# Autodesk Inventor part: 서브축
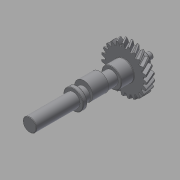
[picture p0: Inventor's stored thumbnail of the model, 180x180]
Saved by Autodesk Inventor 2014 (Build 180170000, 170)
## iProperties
Created: 2016-12
Part Number: 서브축
Material: 강철, 탄소
Document SubType Name: Modeling
Designer: mduedu
Categories: <?xml version="1.0" encoding="UTF-16"?> <MemberInstance><Categories><FamilyTemplate><FamilyTemplateParameter ValueType="xs:double" Id="1" ObjectReferenceKey="da
Density: 7.87 g/cm^3
Appearance: 기본값
Mass: 483.642 g
Surface Area: 167.142 cm^2
Volume: 61.4539 cm^3
CustomPartVersion: 1
Author: mduedu
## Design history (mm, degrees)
sketch "Sketch1"
  geometry: C1 r 28.558 at (0, 0)
  constraints: 1 centre point
  dimensions: "d0" = 57.11622 diameter of C1 (= da_da)
extrude "Extrusion1" new body sketch "Sketch1" distance "d1" = 10 (= da_b); taper "d2" = 0 deg
workplane "Work Plane2"
sketch "Sketch2"
  geometry: C1 r 28.558 at (0, 0) reference; C2 r 26.558 at (0, 0)
  constraints: 1 centre point, 1 coincident
  dimensions: "d3" = 53.11622 diameter of C2 (= da_dw)
feature "피치 지름" sketch "Sketch2" dims "d4" = 10, "d5" = 0
workplane "Work Plane8"
workplane "Work Plane9"
feature "스퍼 기어" dims "da_b" = 10, "da_d" = 53.11622, "da_aw" = 43.87862, "da_da" = 57.11622, "da_df" = 48.11622, "da_dw" = 53.11622, angle "da_beta" = 30 deg, "da_lefttooth" = 10, "da_righttooth" = 0
sketch "스케치3"
  geometry: C1 r 12.5 at (0, 0); 1 further point
  constraints: 1 centre point, 1 coincident
  dimensions: "d49" = 25 diameter of C1
extrude "돌출2" join sketch "스케치3" distance "d50" = 16; taper "d51" = 0 deg
sketch "스케치4"
  geometry: C1 r 8.5 at (0, 0); 1 further point
  constraints: 1 centre point, 1 coincident
  dimensions: "d52" = 17 diameter of C1
extrude "돌출3" join sketch "스케치4" distance "d53" = 103; taper "d54" = 0 deg
sketch "스케치5"
  geometry: C1 r 7.5 at (0, 0); 1 further point
  constraints: 1 centre point, 1 coincident
  dimensions: "d55" = 15 diameter of C1
extrude "돌출4" join sketch "스케치5" distance "d56" = 16; taper "d57" = 0 deg
sketch "스케치6"
  geometry: C1 r 4 at (0, 0); 1 further point
  constraints: 1 centre point, 1 coincident
  dimensions: "d58" = 8 diameter of C1
extrude "돌출5" join sketch "스케치6" distance "d59" = 7; taper "d60" = 0 deg
chamfer "모따기1" distance "d61" = 0.5; stored, may be unused: second distance "d62" = 2, angle "d63" = 45 deg
fillet "모깎기1" dims "d64" = 0.5
node "작업 평면11"
sketch "스케치7"
  geometry: C1 r 11.5 at (0, 3); C2 r 8.5 at (0, 0) reference; 1 further point
  constraints: 1 centre point, 1 tangent, 1 vertical alignment
  dimensions: "d66" = 3 distance of point (0, 0) C1.centre; "d67" = 23 diameter of C1 (derived)
extrude "돌출6" join sketch "스케치7" stored distance "d68" = 20; taper "d69" = 0 deg
node "작업 평면12"
sketch "스케치8"
  geometry: C1 r 12.5 at (0, 0) reference; 1 further point
extrude "돌출7" join sketch "스케치8" distance "d71" = 5; taper "d72" = 0 deg
chamfer "모따기2" distance "d73" = 0.5; stored, may be unused: second distance "d74" = 2, angle "d75" = 45 deg
body "Solid1"
body "Srf1"
other parameters: "d16" = 43.87862 (= da_aw), "d17" = 0, "d34" = 1.36591 (computed from da_z), "d39" = 0, "d41" = 0, "d43" = 43.87862 (= da_aw), "d46" = 43.87862 (= da_aw), "d47" = 0, "d48" = 0, "d65" = 25, "d70" = 48
